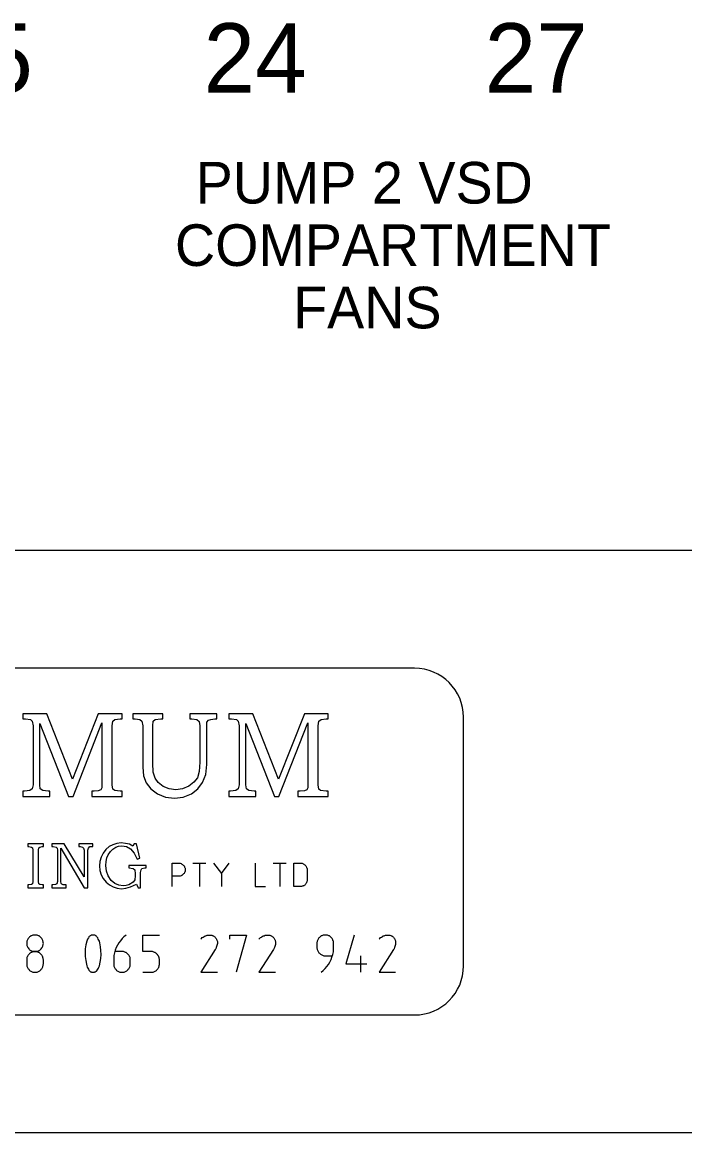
# Model space of a CAD drawing. Extents: x 0 to 841, y 0 to 594.
# Drawn here: x 543.2 to 590.9, y 15 to 95.1 of the extents above; entities that cross this region are included whole.
import ezdxf

# ---------------------------------------------------------------- set-up
doc = ezdxf.new("R2010")
doc.units = 0
for name, color, linetype in [('A1BORDER', 7, 'Continuous'), ('Level 1', 7, 'Continuous'), ('Level 10', 7, 'Continuous')]:
    doc.layers.add(name, color=color, linetype=linetype)

msp = doc.modelspace()

# ---------------------------------------------------------------- linework, layer by layer
at = {"layer": 'A1BORDER'}
for p, q in [((28, 57), (829, 57)), ((829, 15), (28, 15))]:
    msp.add_line(p, q, dxfattribs=at)
at = {"layer": 'Level 1'}
for points in [[(543.59, 35.83), (543.59, 35.63), (543.68, 35.63), (543.87, 35.6), (543.94, 35.55), (543.97, 35.37), (543.97, 33.13), (543.94, 32.95), (543.87, 32.9), (543.68, 32.87), (543.59, 32.87), (543.59, 32.67), (544.74, 32.67), (544.74, 32.87), (544.64, 32.87), (544.47, 32.9), (544.39, 32.95), (544.36, 33.13), (544.36, 35.37), (544.39, 35.55), (544.47, 35.6), (544.64, 35.63), (544.74, 35.63), (544.74, 35.83)], [(545.34, 35.83), (545.34, 35.63), (545.42, 35.63), (545.64, 35.6), (545.72, 35.53), (545.73, 35.37), (545.73, 33.13), (545.69, 32.95), (545.6, 32.9), (545.39, 32.87), (545.34, 32.87), (545.34, 32.67), (546.37, 32.67), (546.37, 32.87), (546.14, 32.87), (546.04, 32.93), (545.99, 32.97), (545.98, 33.13), (545.98, 35.53), (547.66, 32.67), (547.92, 32.67), (547.92, 35.37), (547.96, 35.53), (548.06, 35.63), (548.24, 35.63), (548.29, 35.63), (548.29, 35.83), (547.27, 35.83), (547.27, 35.63), (547.36, 35.63), (547.53, 35.6), (547.62, 35.53), (547.66, 35.37), (547.66, 33.45), (546.23, 35.83)], [(551.26, 35.83), (551.16, 35.67), (550.93, 35.8), (550.64, 35.85), (550.33, 35.9), (550.02, 35.85), (549.73, 35.77), (549.47, 35.63), (549.23, 35.43), (549.03, 35.17), (548.89, 34.87), (548.79, 34.57), (548.77, 34.25), (548.79, 33.9), (548.89, 33.6), (549.03, 33.33), (549.24, 33.07), (549.48, 32.87), (549.74, 32.73), (550.03, 32.63), (550.36, 32.6), (550.67, 32.63), (550.99, 32.73), (551.42, 32.93), (551.54, 32.67), (551.73, 32.67), (551.73, 33.77), (551.76, 33.97), (551.82, 34.05), (552.02, 34.1), (552.12, 34.1), (552.12, 34.27), (550.89, 34.27), (550.89, 34.1), (551.19, 34.05), (551.3, 33.95), (551.34, 33.67), (551.34, 33.53), (551.32, 33.25), (551.19, 33.07), (550.89, 32.87), (550.69, 32.83), (550.48, 32.8), (550.17, 32.85), (549.87, 32.97), (549.6, 33.2), (549.39, 33.53), (549.27, 33.87), (549.22, 34.27), (549.24, 34.55), (549.3, 34.83), (549.4, 35.05), (549.56, 35.27), (549.73, 35.45), (549.93, 35.6), (550.14, 35.67), (550.38, 35.7), (550.7, 35.65), (550.99, 35.47), (551.26, 35.17), (551.48, 34.73), (551.67, 34.8), (551.42, 35.83)]]:
    msp.add_lwpolyline(points, close=True, dxfattribs=at)
for points in [[(554, 32.75), (554, 34.44), (554.48, 34.44), (554.52, 34.44), (554.56, 34.43), (554.59, 34.43), (554.64, 34.41), (554.67, 34.39), (554.7, 34.37), (554.74, 34.35), (554.78, 34.33), (554.8, 34.3), (554.83, 34.26), (554.86, 34.24), (554.88, 34.2), (554.9, 34.16), (554.92, 34.13), (554.93, 34.09), (554.94, 34.05), (554.94, 34.01), (554.94, 33.97), (554.94, 33.93), (554.94, 33.89), (554.93, 33.85), (554.92, 33.81), (554.9, 33.77), (554.88, 33.74), (554.86, 33.7), (554.83, 33.67), (554.8, 33.64), (554.78, 33.61), (554.74, 33.59), (554.7, 33.56), (554.67, 33.55), (554.64, 33.53), (554.59, 33.51), (554.56, 33.51), (554.52, 33.5), (554.48, 33.5), (554, 33.5)], [(555.5, 34.44), (556.44, 34.44)], [(555.98, 34.44), (555.98, 32.75)], [(556.99, 34.44), (557.56, 33.69), (558.12, 34.44)], [(559.98, 34.44), (559.98, 32.75), (560.73, 32.75)], [(561.29, 34.44), (562.23, 34.44)], [(561.77, 34.44), (561.77, 32.75)], [(562.78, 32.75), (562.78, 34.44), (563.26, 34.44), (563.29, 34.44), (563.33, 34.43), (563.37, 34.43), (563.42, 34.41), (563.44, 34.39), (563.48, 34.37), (563.52, 34.35), (563.56, 34.33), (563.58, 34.3), (563.6, 34.26), (563.63, 34.24), (563.66, 34.2), (563.68, 34.16), (563.69, 34.13), (563.7, 34.09), (563.72, 34.05), (563.72, 34.01), (563.72, 33.97), (563.72, 33.23), (563.72, 33.17), (563.72, 33.14), (563.7, 33.1), (563.69, 33.06), (563.68, 33.03), (563.66, 32.99), (563.63, 32.95), (563.6, 32.93), (563.58, 32.89), (563.56, 32.86), (563.52, 32.84), (563.48, 32.81), (563.44, 32.8), (563.42, 32.79), (563.37, 32.77), (563.33, 32.76), (563.29, 32.75), (563.26, 32.75), (562.78, 32.75)], [(557.56, 33.69), (557.56, 32.75)], [(544.12, 28.06), (544.17, 28.06), (544.22, 28.07), (544.27, 28.09), (544.32, 28.1), (544.37, 28.13), (544.42, 28.15), (544.46, 28.17), (544.49, 28.2), (544.53, 28.24), (544.57, 28.27), (544.6, 28.33), (544.63, 28.36), (544.66, 28.41), (544.68, 28.46), (544.69, 28.51), (544.7, 28.56), (544.7, 28.61), (544.72, 28.66), (544.7, 28.71), (544.7, 28.77), (544.69, 28.81), (544.68, 28.86), (544.66, 28.91), (544.63, 28.96), (544.6, 29.01), (544.57, 29.05), (544.53, 29.09), (544.49, 29.13), (544.46, 29.15), (544.42, 29.19), (544.37, 29.2), (544.32, 29.23), (544.27, 29.24), (544.22, 29.25), (544.17, 29.26), (544.12, 29.26), (544.07, 29.26), (544, 29.25), (543.96, 29.24), (543.9, 29.23), (543.86, 29.2), (543.82, 29.19), (543.77, 29.15), (543.73, 29.13), (543.69, 29.09), (543.66, 29.05), (543.62, 29.01), (543.59, 28.96), (543.57, 28.91), (543.56, 28.86), (543.53, 28.81), (543.53, 28.77), (543.52, 28.71), (543.52, 28.66), (543.52, 28.61), (543.53, 28.56), (543.53, 28.51), (543.56, 28.46), (543.57, 28.41), (543.59, 28.36), (543.62, 28.33), (543.66, 28.27), (543.69, 28.24), (543.73, 28.2), (543.77, 28.17), (543.82, 28.15), (543.86, 28.13), (543.9, 28.1), (543.96, 28.09), (544, 28.07), (544.07, 28.06), (544.12, 28.06)], [(548, 26.73), (548.02, 26.7), (548.04, 26.67), (548.07, 26.65), (548.09, 26.64), (548.12, 26.61), (548.16, 26.6), (548.18, 26.59), (548.22, 26.59), (548.24, 26.57), (548.28, 26.57), (548.3, 26.57), (548.34, 26.57), (548.38, 26.57), (548.4, 26.59), (548.43, 26.6), (548.47, 26.61), (548.49, 26.63), (548.52, 26.65), (548.54, 26.66), (548.57, 26.69), (548.59, 26.71), (548.6, 26.73), (548.64, 26.79), (548.69, 26.86), (548.72, 26.94), (548.76, 27.03), (548.82, 27.3), (548.86, 27.57), (548.88, 27.85), (548.87, 28.14), (548.84, 28.41), (548.78, 28.69), (548.76, 28.81), (548.72, 28.9), (548.68, 28.97), (548.64, 29.05), (548.6, 29.11), (548.58, 29.14), (548.56, 29.16), (548.53, 29.19), (548.5, 29.2), (548.48, 29.23), (548.44, 29.24), (548.42, 29.24), (548.38, 29.25), (548.36, 29.26), (548.32, 29.26), (548.29, 29.26), (548.26, 29.26), (548.23, 29.25), (548.19, 29.25), (548.17, 29.24), (548.13, 29.23), (548.1, 29.21), (548.08, 29.19), (548.06, 29.17), (548.03, 29.15), (548, 29.13), (548, 29.11), (547.96, 29.05), (547.9, 28.96), (547.88, 28.89), (547.86, 28.81), (547.78, 28.54), (547.74, 28.26), (547.73, 27.97), (547.73, 27.7), (547.77, 27.43), (547.82, 27.15), (547.86, 27.03), (547.88, 26.94), (547.92, 26.86), (547.96, 26.79), (548, 26.73)], [(550.68, 29.26), (550.53, 29.14), (550.39, 29), (550.27, 28.85), (550.16, 28.7), (550.06, 28.53), (549.97, 28.35), (549.9, 28.16), (549.84, 27.97), (549.8, 27.79), (549.79, 27.6), (549.79, 27.47), (549.79, 27.17), (549.79, 27.13), (549.79, 27.06), (549.8, 27.01), (549.83, 26.96), (549.84, 26.91), (549.87, 26.87), (549.89, 26.83), (549.93, 26.79), (549.97, 26.75), (550, 26.71), (550.04, 26.67), (550.09, 26.65), (550.13, 26.63), (550.18, 26.61), (550.23, 26.59), (550.28, 26.59), (550.33, 26.57), (550.39, 26.57), (550.44, 26.57), (550.49, 26.59), (550.54, 26.59), (550.59, 26.61), (550.64, 26.63), (550.68, 26.65), (550.73, 26.67), (550.77, 26.71), (550.8, 26.75), (550.84, 26.79), (550.88, 26.83), (550.9, 26.87), (550.93, 26.91), (550.94, 26.96), (550.97, 27.01), (550.97, 27.06), (550.98, 27.13), (550.98, 27.17), (550.98, 27.47), (550.98, 27.53), (550.97, 27.57), (550.97, 27.63), (550.94, 27.67), (550.93, 27.73), (550.9, 27.77), (550.88, 27.81), (550.84, 27.85), (550.8, 27.89), (550.77, 27.93), (550.73, 27.96), (550.68, 27.99), (550.64, 28.01), (550.59, 28.03), (550.54, 28.05), (550.49, 28.06), (550.44, 28.06), (550.39, 28.06), (549.94, 28.06)], [(551.89, 26.57), (552.49, 26.57), (552.54, 26.57), (552.59, 26.59), (552.64, 26.59), (552.69, 26.61), (552.74, 26.63), (552.78, 26.65), (552.83, 26.67), (552.87, 26.71), (552.9, 26.75), (552.94, 26.79), (552.98, 26.83), (553, 26.87), (553.03, 26.91), (553.04, 26.96), (553.07, 27.01), (553.07, 27.06), (553.08, 27.13), (553.08, 27.17), (553.08, 27.47), (553.08, 27.53), (553.07, 27.57), (553.07, 27.63), (553.04, 27.67), (553.03, 27.73), (553, 27.77), (552.98, 27.81), (552.94, 27.85), (552.9, 27.89), (552.87, 27.93), (552.83, 27.96), (552.78, 27.99), (552.74, 28.01), (552.69, 28.03), (552.64, 28.05), (552.59, 28.06), (552.54, 28.06), (552.49, 28.06), (551.89, 28.06), (551.89, 29.26), (553.08, 29.26)], [(556.07, 28.96), (556.12, 29.01), (556.17, 29.07), (556.23, 29.11), (556.3, 29.15), (556.37, 29.19), (556.44, 29.21), (556.52, 29.24), (556.59, 29.25), (556.67, 29.26), (556.7, 29.26), (556.76, 29.26), (556.8, 29.25), (556.86, 29.24), (556.9, 29.23), (556.94, 29.21), (556.99, 29.19), (557.03, 29.16), (557.07, 29.13), (557.1, 29.1), (557.13, 29.05), (557.17, 29.01), (557.19, 28.97), (557.2, 28.94), (557.23, 28.89), (557.24, 28.84), (557.26, 28.79), (557.26, 28.75), (557.26, 28.7), (557.26, 28.66), (557.24, 28.57), (557.23, 28.5), (557.2, 28.43), (557.18, 28.35), (557.14, 28.27), (557.1, 28.21), (556.07, 26.57), (557.26, 26.57)], [(558.17, 28.96), (558.17, 29.26), (559.36, 29.26), (558.62, 26.57)], [(560.26, 28.96), (560.3, 29.01), (560.37, 29.07), (560.43, 29.11), (560.49, 29.15), (560.56, 29.19), (560.63, 29.21), (560.7, 29.24), (560.78, 29.25), (560.86, 29.26), (560.89, 29.26), (560.94, 29.26), (560.99, 29.25), (561.04, 29.24), (561.09, 29.23), (561.13, 29.21), (561.18, 29.19), (561.22, 29.16), (561.26, 29.13), (561.29, 29.1), (561.32, 29.05), (561.36, 29.01), (561.38, 28.97), (561.4, 28.94), (561.42, 28.89), (561.43, 28.84), (561.44, 28.79), (561.46, 28.75), (561.46, 28.7), (561.46, 28.66), (561.44, 28.57), (561.42, 28.5), (561.39, 28.43), (561.37, 28.35), (561.33, 28.27), (561.3, 28.21), (560.26, 26.57), (561.46, 26.57)], [(564.74, 26.57), (564.89, 26.7), (565.03, 26.84), (565.16, 26.99), (565.27, 27.14), (565.37, 27.31), (565.46, 27.49), (565.52, 27.66), (565.58, 27.85), (565.62, 28.05), (565.63, 28.24), (565.63, 28.36), (565.63, 28.66), (565.63, 28.71), (565.63, 28.77), (565.62, 28.81), (565.59, 28.86), (565.58, 28.91), (565.56, 28.96), (565.53, 29.01), (565.49, 29.05), (565.46, 29.09), (565.42, 29.13), (565.38, 29.15), (565.34, 29.19), (565.29, 29.2), (565.24, 29.23), (565.19, 29.24), (565.14, 29.25), (565.09, 29.26), (565.04, 29.26), (564.98, 29.26), (564.93, 29.25), (564.88, 29.24), (564.83, 29.23), (564.78, 29.2), (564.74, 29.19), (564.69, 29.15), (564.66, 29.13), (564.62, 29.09), (564.58, 29.05), (564.54, 29.01), (564.52, 28.96), (564.49, 28.91), (564.48, 28.86), (564.46, 28.81), (564.46, 28.77), (564.44, 28.71), (564.44, 28.66), (564.44, 28.36), (564.44, 28.31), (564.46, 28.26), (564.46, 28.21), (564.48, 28.16), (564.49, 28.11), (564.52, 28.06), (564.54, 28.03), (564.58, 27.97), (564.62, 27.94), (564.66, 27.91), (564.69, 27.87), (564.74, 27.85), (564.78, 27.83), (564.83, 27.8), (564.88, 27.79), (564.93, 27.77), (564.98, 27.77), (565.04, 27.77), (565.49, 27.77)], [(567.13, 29.26), (566.53, 27.17), (568.02, 27.17)], [(568.92, 28.96), (568.97, 29.01), (569.02, 29.07), (569.08, 29.11), (569.16, 29.15), (569.22, 29.19), (569.29, 29.21), (569.37, 29.24), (569.44, 29.25), (569.52, 29.26), (569.56, 29.26), (569.6, 29.26), (569.66, 29.25), (569.7, 29.24), (569.76, 29.23), (569.79, 29.21), (569.84, 29.19), (569.88, 29.16), (569.92, 29.13), (569.96, 29.1), (569.98, 29.05), (570.02, 29.01), (570.04, 28.97), (570.06, 28.94), (570.08, 28.89), (570.09, 28.84), (570.1, 28.79), (570.1, 28.75), (570.1, 28.7), (570.1, 28.66), (570.09, 28.57), (570.08, 28.5), (570.06, 28.43), (570.03, 28.35), (569.99, 28.27), (569.96, 28.21), (568.92, 26.57), (570.1, 26.57)], [(543.52, 27.17), (543.52, 27.13), (543.53, 27.06), (543.53, 27.01), (543.56, 26.96), (543.57, 26.91), (543.59, 26.87), (543.62, 26.83), (543.66, 26.79), (543.69, 26.75), (543.73, 26.71), (543.77, 26.67), (543.82, 26.65), (543.86, 26.63), (543.9, 26.61), (543.96, 26.59), (544, 26.59), (544.07, 26.57), (544.12, 26.57), (544.17, 26.57), (544.22, 26.59), (544.27, 26.59), (544.32, 26.61), (544.37, 26.63), (544.42, 26.65), (544.46, 26.67), (544.49, 26.71), (544.53, 26.75), (544.57, 26.79), (544.6, 26.83), (544.63, 26.87), (544.66, 26.91), (544.68, 26.96), (544.69, 27.01), (544.7, 27.06), (544.7, 27.13), (544.72, 27.17), (544.72, 27.47), (544.7, 27.53), (544.7, 27.57), (544.69, 27.63), (544.68, 27.67), (544.66, 27.73), (544.63, 27.77), (544.6, 27.81), (544.57, 27.85), (544.53, 27.89), (544.49, 27.93), (544.46, 27.96), (544.42, 27.99), (544.37, 28.01), (544.32, 28.03), (544.27, 28.05), (544.22, 28.06), (544.17, 28.06), (544.12, 28.06), (544.07, 28.06), (544, 28.06), (543.96, 28.05), (543.9, 28.03), (543.86, 28.01), (543.82, 27.99), (543.77, 27.96), (543.73, 27.93), (543.69, 27.89), (543.66, 27.85), (543.62, 27.81), (543.59, 27.77), (543.57, 27.73), (543.56, 27.67), (543.53, 27.63), (543.53, 27.57), (543.52, 27.53), (543.52, 27.47), (543.52, 27.17)], [(567.58, 27.77), (567.58, 26.57)]]:
    msp.add_lwpolyline(points, dxfattribs=at)
at = {"layer": 'Level 10'}
for p, q in [((571.47, 48.5), (513.54, 48.5)), ((575, 27.03), (575, 44.97)), ((513.54, 23.5), (571.47, 23.5))]:
    msp.add_line(p, q, dxfattribs=at)
for points in [[(543.23, 45.2), (543.23, 44.85), (543.43, 44.85), (543.78, 44.8), (543.92, 44.67), (543.98, 44.35), (543.98, 40.1), (543.92, 39.8), (543.74, 39.67), (543.36, 39.63), (543.23, 39.63), (543.23, 39.25), (545.18, 39.25), (545.18, 39.63), (545.06, 39.63), (544.67, 39.67), (544.5, 39.8), (544.46, 40.1), (544.46, 44.5), (546.52, 39.25), (546.86, 39.25), (548.94, 44.57), (548.94, 40.1), (548.93, 39.87), (548.86, 39.73), (548.68, 39.65), (548.38, 39.63), (548.22, 39.63), (548.22, 39.25), (550.39, 39.25), (550.39, 39.63), (550.26, 39.63), (549.87, 39.67), (549.72, 39.77), (549.67, 40.1), (549.67, 44.35), (549.72, 44.67), (549.88, 44.8), (550.26, 44.85), (550.39, 44.85), (550.39, 45.2), (548.68, 45.2), (546.82, 40.5), (544.97, 45.2)], [(551.16, 45.2), (551.16, 44.85), (551.34, 44.85), (551.68, 44.8), (551.82, 44.67), (551.88, 44.35), (551.88, 41.35), (551.93, 40.73), (552.13, 40.23), (552.46, 39.8), (552.94, 39.43), (553.52, 39.2), (554.16, 39.13), (554.8, 39.2), (555.39, 39.43), (555.86, 39.8), (556.2, 40.25), (556.42, 40.83), (556.49, 41.55), (556.49, 44.35), (556.5, 44.6), (556.62, 44.75), (556.79, 44.8), (557.07, 44.85), (557.22, 44.85), (557.22, 45.2), (555.27, 45.2), (555.27, 44.85), (555.43, 44.85), (555.78, 44.8), (555.94, 44.65), (555.99, 44.35), (555.99, 41.73), (555.94, 41.05), (555.82, 40.6), (555.57, 40.27), (555.2, 40), (554.74, 39.8), (554.27, 39.73), (553.78, 39.8), (553.36, 39.97), (553, 40.25), (552.78, 40.57), (552.64, 41), (552.6, 41.65), (552.6, 44.35), (552.64, 44.67), (552.78, 44.8), (553.18, 44.85), (553.33, 44.85), (553.33, 45.2)], [(558.08, 45.2), (558.08, 44.85), (558.28, 44.85), (558.63, 44.8), (558.77, 44.67), (558.82, 44.35), (558.82, 40.1), (558.77, 39.8), (558.59, 39.67), (558.2, 39.63), (558.08, 39.63), (558.08, 39.25), (560.03, 39.25), (560.03, 39.63), (559.9, 39.63), (559.52, 39.67), (559.36, 39.8), (559.3, 40.1), (559.3, 44.5), (561.37, 39.25), (561.7, 39.25), (563.79, 44.57), (563.79, 40.1), (563.77, 39.87), (563.7, 39.73), (563.53, 39.65), (563.23, 39.63), (563.07, 39.63), (563.07, 39.25), (565.24, 39.25), (565.24, 39.63), (565.09, 39.63), (564.7, 39.67), (564.57, 39.77), (564.52, 40.1), (564.52, 44.35), (564.57, 44.67), (564.73, 44.8), (565.09, 44.85), (565.24, 44.85), (565.24, 45.2), (563.53, 45.2), (561.67, 40.5), (559.82, 45.2)]]:
    msp.add_lwpolyline(points, close=True, dxfattribs=at)
for centre, start, end in [((571.46545, 44.96253), 0, 90), ((571.46545, 27.03003), 270, 0)]:
    msp.add_arc(centre, 3.535, start, end, dxfattribs=at)

# ---------------------------------------------------------------- texts
at = {"layer": 'Level 1'}
for s, height, p in [('25', 4.99998, (536.52, 90)), ('24', 4.99998, (556.26466, 90)), ('27', 4.99998, (576.52, 90)), ('PUMP 2 VSD', 3, (555.69629, 82)), ('COMPARTMENT', 3, (554.20215, 77.5)), ('FANS', 3, (562.71875, 73))]:
    msp.add_text(s, height=height, dxfattribs=at).set_placement(p)

doc.saveas('drawing.dxf')
